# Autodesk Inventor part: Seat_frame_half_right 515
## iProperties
Shininess: 69.0
Length Units: 11269
Angle Units: 11279
Time Units: 11290
Mass Units: 11283
Length Display Precision: 3
Angle Display Precision: 2
Created: 2001-04
Part Number: Seat_frame_half_right 515
Material: Standard
Document SubType Name: Modellieren
Designer: dl
Density: 1 g/cm^3
Density: 0.0
Volumn: 0.0
Area: 0.0
PropertySet Name: Model Information
Control State: 0
Master: False
Checked Out: False
Author: dl
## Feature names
1. Sweep1
2. Extrusion1
3. Fillet1
4. Rectangular Pattern1
5. Extrusion2
6. Extrusion3
